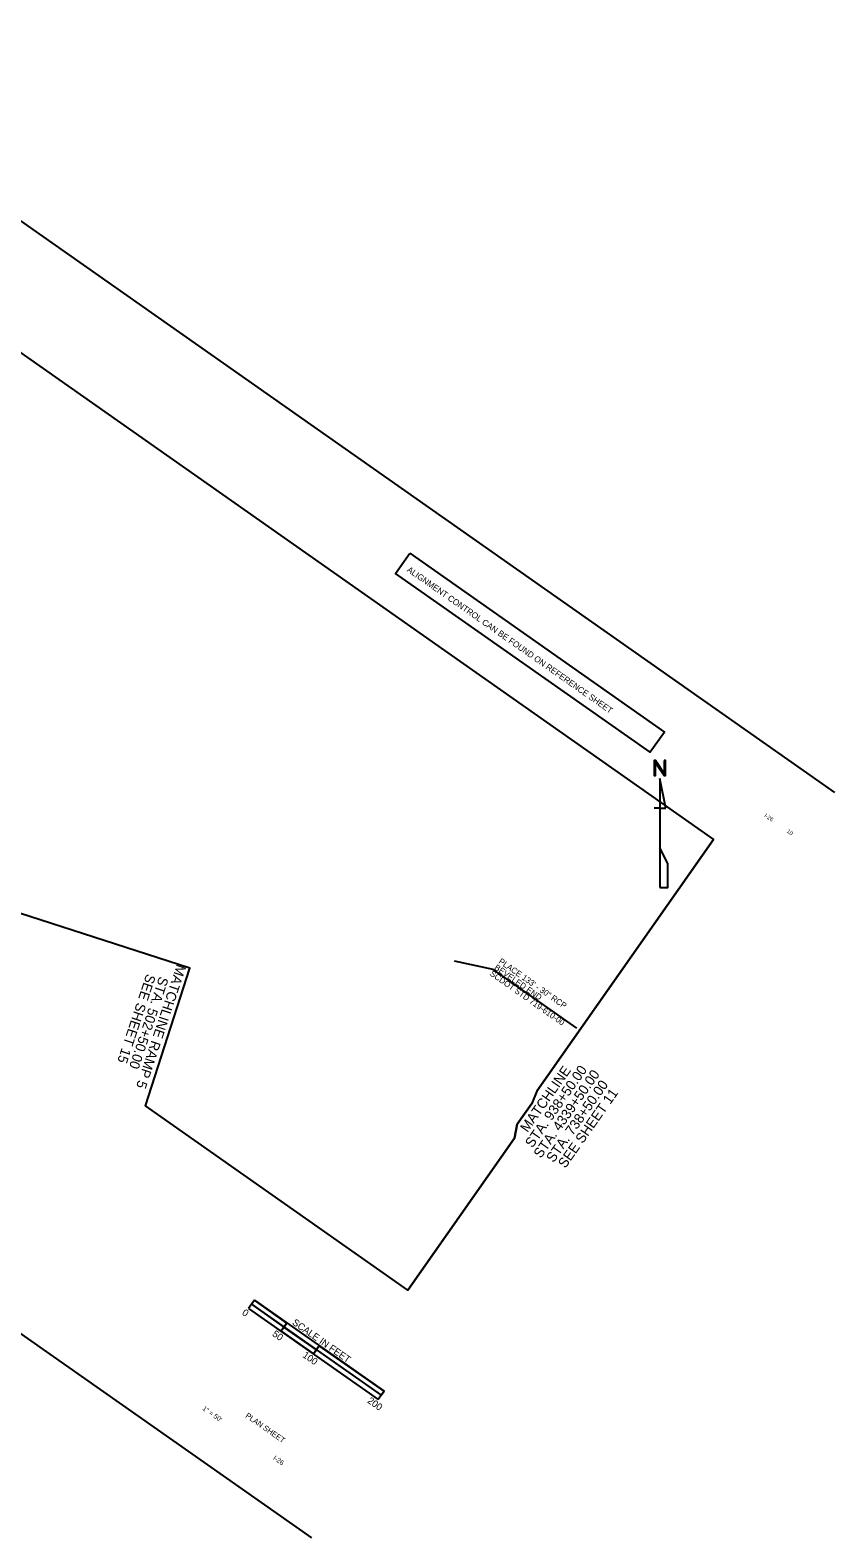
# Model space of a CAD drawing. Extents: x 2221439 to 2223471, y 467578 to 469482.
# Drawn here: x 2222455 to 2223471, y 467578 to 469482 of the extents above; entities that cross this region are included whole.
import ezdxf

# ---------------------------------------------------------------- set-up
doc = ezdxf.new("R2010")
doc.units = 0
for name, color, linetype in [('North Arrow', 7, 'Continuous'), ('RD_HY_Misc', 7, 'Continuous'), ('RD_SHT_MatchLine', 7, 'Continuous'), ('RD_SHT_ShtClip', 7, 'Continuous'), ('RD_SHT_TX', 7, 'Continuous')]:
    doc.layers.add(name, color=color, linetype=linetype)

msp = doc.modelspace()

# ---------------------------------------------------------------- linework, layer by layer
at = {"layer": 'North Arrow'}
for p, q in [((2223250.2, 468537), (2223250.2, 468499.5)), ((2223257.7, 468499.5), (2223250.2, 468537)), ((2223250.2, 468499.5), (2223242.7, 468499.5)), ((2223250.2, 468499.5), (2223250.2, 468449.5)), ((2223250.2, 468499.5), (2223257.7, 468499.5)), ((2223250.2, 468449.5), (2223250.2, 468399.5))]:
    msp.add_line(p, q, dxfattribs=at)
for points in [[(2223243, 468543.5), (2223243, 468540.8), (2223244.7, 468540.8), (2223244.7, 468543.5), (2223244.7, 468556.9), (2223246.7, 468556.9), (2223245, 468559.6), (2223243, 468559.6), (2223243, 468556.9)], [(2223253.6, 468543.5), (2223255.4, 468540.8), (2223257.3, 468540.8), (2223257.3, 468543.5), (2223255.6, 468543.5), (2223246.7, 468556.9), (2223244.7, 468556.9)], [(2223255.6, 468559.6), (2223255.6, 468543.5), (2223257.3, 468543.5), (2223257.3, 468559.6)]]:
    msp.add_lwpolyline(points, close=True, dxfattribs=at)
msp.add_lwpolyline([(2223250.2, 468399.5), (2223260.2, 468399.5), (2223260.2, 468429.5), (2223250.2, 468449.5)], dxfattribs=at)
at = {"layer": 'RD_HY_Misc'}
msp.add_line((2223145.3, 468221.8), (2223039.7, 468296), dxfattribs=at)
msp.add_lwpolyline([(2223039.7, 468296), (2222990.9, 468306.2)], dxfattribs=at)
at = {"layer": 'RD_SHT_MatchLine'}
for p, q in [((2223094.6, 468142.3), (2223317.8, 468460.2)), ((2222600.7, 468123.6), (2222656.6, 468297.6)), ((2223070, 468100.4), (2223088.2, 468126.5)), ((2223094.6, 468142.3), (2223088.2, 468126.5)), ((2223066.6, 468082.9), (2223070, 468100.4)), ((2222931.9, 467891), (2223066.6, 468082.9))]:
    msp.add_line(p, q, dxfattribs=at)
at = {"layer": 'RD_SHT_ShtClip'}
msp.add_lwpolyline([(2222043.7, 469082.4), (2222295.6, 469177.9), (2223317.8, 468460.2), (2223094.6, 468142.3), (2223088.2, 468126.5), (2223070, 468100.4), (2223066.6, 468082.9), (2222999.3, 467986.9), (2222931.9, 467891), (2222600.7, 468123.6), (2222656.6, 468297.6), (2222320.1, 468406), (2221748.3, 468807.4), (2221827.8, 468929.8), (2221829.7, 468942.5), (2221854.3, 468980.4), (2221862, 468995.5), (2221952, 469134.1)], close=True, dxfattribs=at)
at = {"layer": 'RD_SHT_TX'}
for p, q in [((2223470.9, 468519.5), (2222100, 469481.9)), ((2221439.3, 468540.7), (2222810.1, 467578.3)), ((2222738.1, 467878.3), (2222730.9, 467868)), ((2222730.9, 467868), (2222894.6, 467753.1)), ((2222738.1, 467878.3), (2222734.5, 467873.2)), ((2222734.5, 467873.2), (2222898.2, 467758.2)), ((2222734.5, 467873.2), (2222775.4, 467844.4)), ((2222738.1, 467878.3), (2222901.8, 467763.4)), ((2222779, 467849.5), (2222738.1, 467878.3)), ((2222779, 467849.5), (2222771.9, 467839.3)), ((2222775.4, 467844.4), (2222771.9, 467839.3)), ((2222775.4, 467844.4), (2222779, 467849.5)), ((2222816.4, 467815.7), (2222775.4, 467844.4)), ((2222771.9, 467839.3), (2222812.8, 467810.6)), ((2222820, 467820.8), (2222812.8, 467810.6)), ((2222812.8, 467810.6), (2222816.4, 467815.7)), ((2222820, 467820.8), (2222816.4, 467815.7)), ((2222816.4, 467815.7), (2222898.2, 467758.2)), ((2222901.8, 467763.4), (2222820, 467820.8)), ((2222901.8, 467763.4), (2222894.6, 467753.1)), ((2222898.2, 467758.2), (2222901.8, 467763.4))]:
    msp.add_line(p, q, dxfattribs=at)
msp.add_lwpolyline([(2222934.2, 468821.4), (2223255.7, 468595.6), (2223237.9, 468570.2), (2222916.4, 468795.9)], close=True, dxfattribs=at)

# ---------------------------------------------------------------- texts
at = {"layer": 'RD_HY_Misc'}
for s, p in [('BEVELED END', (2223040.3, 468296.8)), ('PLACE 133\' - 30" RCP', (2223045.7, 468304.5)), ('SCDOT STD 719-610-00', (2223034.8, 468289))]:
    msp.add_text(s, height=7.5, rotation=324.929, dxfattribs=at).set_placement(p)
at = {"layer": 'RD_SHT_MatchLine'}
for s, rotation, p in [('MATCHLINE RAMP 5', 251.5448, (2222640.4, 468303.1)), ('SEE SHEET 15', 251.5448, (2222602, 468291)), ('STA. 502+50.00', 251.5448, (2222618.2, 468287.9)), ('MATCHLINE', 54.929, (2223082.9, 468089.4)), ('STA. 938+50.00', 54.929, (2223089.1, 468069.9)), ('STA. 4339+50.00', 54.929, (2223099.8, 468056.7)), ('STA. 738+50.00', 54.929, (2223115.8, 468051.2)), ('SEE SHEET 11', 54.929, (2223130.7, 468044.1))]:
    msp.add_text(s, height=12.5, rotation=rotation, dxfattribs=at).set_placement(p)
at = {"layer": 'RD_SHT_TX'}
for s, height, p in [('ALIGNMENT CONTROL CAN BE FOUND ON REFERENCE SHEET', 7.656, (2222930.1, 468799)), ('I-26', 5, (2223381.4, 468489.1)), ('10', 5, (2223409.7, 468469.3)), ('0', 8.75, (2222721.7, 467860.7)), ('50', 8.75, (2222760, 467833.9)), ('SCALE IN FEET', 8.75, (2222785.1, 467848.3)), ('100', 8.75, (2222798.2, 467807.1)), ('200', 8.75, (2222880, 467749.6)), ('1" = 50\'', 6, (2222672, 467740.3)), ('PLAN SHEET', 7, (2222726.2, 467731)), ('I-26', 6, (2222761.2, 467677.7))]:
    msp.add_text(s, height=height, rotation=324.929, dxfattribs=at).set_placement(p)

doc.saveas('drawing.dxf')
